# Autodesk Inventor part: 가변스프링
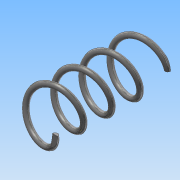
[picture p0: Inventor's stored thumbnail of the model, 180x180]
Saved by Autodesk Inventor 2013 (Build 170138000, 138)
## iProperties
Created: 2015-09
Part Number: 가변스프링
Material: 강철, 탄소
Document SubType Name: Modeling
Designer: Administrator
Mass: 4.92073 g
Surface Area: 12.7437 cm^2
Volume: 0.625251 cm^3
Density: 7.87 g/cm^3
Author: Administrator
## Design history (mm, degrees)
sketch "스케치1"
  geometry: L1 (0, 0)-(0, 42); L2 (0, 0)-(8, 0); L3 (0, 42)-(8, 42); C1 r 1 at (8, 0)
  constraints: 6 end point, 1 centre point, 1 horizontal alignment, 1 parallel, 1 perpendicular, 1 vertical
  dimensions: "d0" = 42 distance of L1.start L1.end (derived); "d1" = 2 diameter of C1; "d2" = 16 diameter of L2.end L1; "d3" = 8 distance of L1.end L3.end
feature "코일1" sketch "스케치1" pitch "d4" = 10; turns "d6" = 4; dims "d5" = 42 (= d0), "d7" = 0, angle "d8" = 90 deg, angle "d9" = 90 deg, "d10" = 0, "d11" = 0
sketch "스케치2"
  geometry: L1 (42, 10)-(0, 10); L2 (0, 10)-(0, -10); L3 (0, -10)-(42, -10); L4 (42, -10)-(42, 10); 2 further points
  constraints: 8 end point, 2 parallel, 1 coincident, 1 horizontal, 1 midpoint, 1 perpendicular
  dimensions: "d12" = 20 distance of L3.end L1.start; "d14" = 42 distance of L1.start L1.end (derived)
extrude "돌출1" sketch "스케치2" stored distance "d15" = 10; taper "d16" = 0 deg
node "솔리드1"
